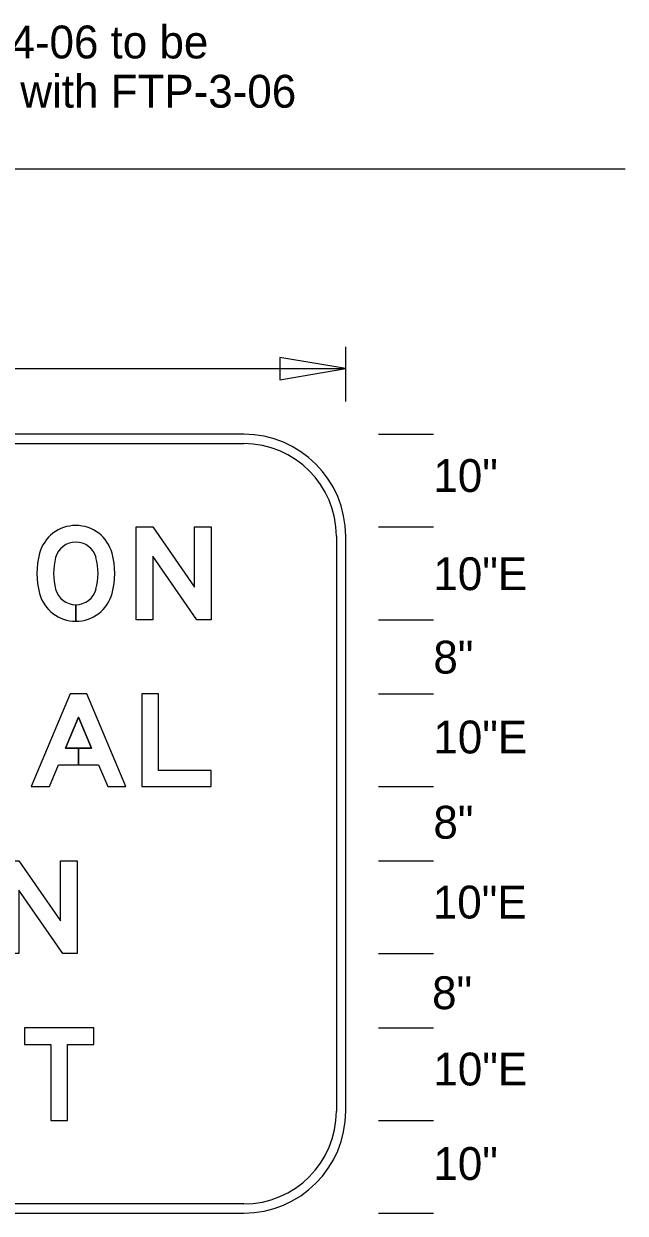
# Model space of a CAD drawing. Extents: x 0 to 770, y 0 to 495.
# Drawn here: x 705.9 to 770, y 218.8 to 345.5 of the extents above; entities that cross this region are included whole.
import ezdxf

# ---------------------------------------------------------------- set-up
doc = ezdxf.new("R2010")
doc.units = 0
for name, color, linetype in [('Dimension', 7, 'Continuous'), ('GSBWFill', 7, 'Continuous'), ('GSColorFill', 7, 'Continuous'), ('GSDims', 7, 'Continuous'), ('GSOutline', 7, 'Continuous'), ('SheetLines_dp', 7, 'Continuous'), ('TextStructures', 7, 'Continuous')]:
    doc.layers.add(name, color=color, linetype=linetype)

msp = doc.modelspace()

# ---------------------------------------------------------------- linework, layer by layer
at = {"layer": 'Dimension'}
msp.add_lwpolyline([(740.23, 308.76), (733.22, 309.95), (733.22, 307.57)], close=True, dxfattribs=at)
at = {"layer": 'GSBWFill'}
for p, q in [((729.36, 301.76), (608.82, 301.76)), ((729.36, 301.76), (608.82, 301.76)), ((608.82, 300.77), (729.36, 300.77)), ((739.25, 290.89), (739.25, 229.63)), ((740.23, 229.63), (740.23, 290.89)), ((740.23, 229.63), (740.23, 290.89)), ((711.48, 281.82), (711.48, 283.6)), ((711.48, 283.6), (711.48, 281.82)), ((729.36, 219.75), (608.83, 219.75)), ((608.82, 218.76), (729.36, 218.76)), ((608.83, 218.76), (729.36, 218.76))]:
    msp.add_line(p, q, dxfattribs=at)
for points in [[(725.91, 291.88), (725.91, 281.99), (724.37, 281.99), (719.68, 288.76), (719.68, 281.99), (717.9, 281.99), (717.9, 291.88), (719.69, 291.88), (724.13, 285.47), (724.13, 291.88)], [(713.16, 268.31), (711.78, 268.31), (711.78, 266.53), (713.91, 266.53), (714.89, 264.21), (716.82, 264.21), (712.67, 274.09), (710.89, 274.09), (706.74, 264.21), (708.67, 264.21), (709.64, 266.53), (711.78, 266.53), (711.78, 268.31), (710.39, 268.31), (711.78, 271.61)], [(725.91, 264.21), (725.91, 265.94), (720.27, 265.94), (720.27, 274.09), (718.5, 274.09), (718.5, 264.21)], [(711.63, 256.3), (711.63, 246.42), (710.1, 246.42), (705.4, 253.19), (705.4, 246.42), (703.62, 246.42), (703.62, 256.3), (705.41, 256.3), (709.85, 249.9), (709.85, 256.3)], [(706, 236.74), (708.81, 236.74), (708.81, 228.64), (710.59, 228.64), (710.59, 236.74), (713.41, 236.74), (713.41, 238.52), (706, 238.52)]]:
    msp.add_lwpolyline(points, close=True, dxfattribs=at)
for centre, radius, start, end in [((729.36, 290.89), 10.87, 0, 90), ((729.36, 290.89), 10.87, 0, 90), ((729.36, 290.89), 9.88, 0, 90), ((729.36, 229.63), 10.87, 270, 0), ((729.36, 229.63), 9.88, 270, 0), ((729.36, 229.63), 10.87, 270, 0)]:
    msp.add_arc(centre, radius, start, end, dxfattribs=at)
for centre, major_axis, start_param, end_param in [((711.48, 288.04), (0, 4), 4.973521, 7.592849), ((711.48, 288.04), (0, 2.23), 4.973521, 7.592849), ((715.63, 286.93), (0, 8.3), 1.309664, 1.831929), ((707.33, 286.93), (0, 8.3), 4.451257, 4.973521), ((715.63, 286.93), (0, 6.52), 1.309664, 1.831929), ((707.33, 286.93), (0, 6.52), 4.451257, 4.973521), ((711.48, 285.83), (0, 2.23), 1.831929, 3.141593), ((711.48, 285.83), (0, 2.23), 3.141815, 4.451257), ((711.48, 285.83), (0, 4), 1.831929, 3.141593), ((711.48, 285.83), (0, 4), 3.141716, 4.451257)]:
    msp.add_ellipse(centre, major_axis=major_axis, ratio=0.999994, start_param=start_param, end_param=end_param, dxfattribs=at)
at = {"layer": 'GSColorFill'}
for p, q in [((711.48, 281.82), (711.48, 283.6)), ((711.48, 283.6), (711.48, 281.82))]:
    msp.add_line(p, q, dxfattribs=at)
for points in [[(725.91, 291.88), (725.91, 281.99), (724.37, 281.99), (719.68, 288.76), (719.68, 281.99), (717.9, 281.99), (717.9, 291.88), (719.69, 291.88), (724.13, 285.47), (724.13, 291.88)], [(713.16, 268.31), (711.78, 268.31), (711.78, 266.53), (713.91, 266.53), (714.89, 264.21), (716.82, 264.21), (712.67, 274.09), (710.89, 274.09), (706.74, 264.21), (708.67, 264.21), (709.64, 266.53), (711.78, 266.53), (711.78, 268.31), (710.39, 268.31), (711.78, 271.61)], [(725.91, 264.21), (725.91, 265.94), (720.27, 265.94), (720.27, 274.09), (718.5, 274.09), (718.5, 264.21)], [(711.63, 256.3), (711.63, 246.42), (710.1, 246.42), (705.4, 253.19), (705.4, 246.42), (703.62, 246.42), (703.62, 256.3), (705.41, 256.3), (709.85, 249.9), (709.85, 256.3)], [(706, 236.74), (708.81, 236.74), (708.81, 228.64), (710.59, 228.64), (710.59, 236.74), (713.41, 236.74), (713.41, 238.52), (706, 238.52)]]:
    msp.add_lwpolyline(points, close=True, dxfattribs=at)
for centre, major_axis, start_param, end_param in [((711.48, 288.04), (0, 4), 4.973521, 7.592849), ((711.48, 288.04), (0, 2.23), 4.973521, 7.592849), ((715.63, 286.93), (0, 8.3), 1.309664, 1.831929), ((707.33, 286.93), (0, 8.3), 4.451257, 4.973521), ((715.63, 286.93), (0, 6.52), 1.309664, 1.831929), ((707.33, 286.93), (0, 6.52), 4.451257, 4.973521), ((711.48, 285.83), (0, 2.23), 1.831929, 3.141593), ((711.48, 285.83), (0, 2.23), 3.141815, 4.451257), ((711.48, 285.83), (0, 4), 1.831929, 3.141593), ((711.48, 285.83), (0, 4), 3.141716, 4.451257)]:
    msp.add_ellipse(centre, major_axis=major_axis, ratio=0.999994, start_param=start_param, end_param=end_param, dxfattribs=at)
at = {"layer": 'GSDims'}
for p, q in [((740.23, 305.26), (740.23, 311.09)), ((597.95, 308.76), (740.23, 308.76)), ((743.73, 301.76), (749.57, 301.76)), ((743.73, 291.88), (749.57, 291.88)), ((743.73, 291.88), (749.57, 291.88)), ((743.73, 281.99), (749.57, 281.99)), ((743.73, 281.99), (749.57, 281.99)), ((743.73, 274.09), (749.57, 274.09)), ((743.73, 274.09), (749.57, 274.09)), ((743.73, 264.21), (749.57, 264.21)), ((743.73, 264.21), (749.57, 264.21)), ((743.73, 256.3), (749.57, 256.3)), ((743.73, 256.3), (749.57, 256.3)), ((743.73, 246.42), (749.57, 246.42)), ((743.73, 246.42), (749.57, 246.42)), ((743.73, 238.52), (749.57, 238.52)), ((743.73, 238.52), (749.57, 238.52)), ((743.73, 228.64), (749.57, 228.64)), ((743.73, 228.64), (749.57, 228.64)), ((743.73, 218.76), (749.57, 218.76))]:
    msp.add_line(p, q, dxfattribs=at)
at = {"layer": 'GSOutline'}
for points in [[(725.91, 291.88), (725.91, 281.99), (724.37, 281.99), (719.68, 288.76), (719.68, 281.99), (717.9, 281.99), (717.9, 291.88), (719.69, 291.88), (724.13, 285.47), (724.13, 291.88)], [(709.64, 266.53), (713.91, 266.53), (714.89, 264.21), (716.82, 264.21), (712.67, 274.09), (710.89, 274.09), (706.74, 264.21), (708.67, 264.21)], [(725.91, 264.21), (725.91, 265.94), (720.27, 265.94), (720.27, 274.09), (718.5, 274.09), (718.5, 264.21)], [(713.16, 268.31), (711.78, 271.61), (710.39, 268.31)], [(711.63, 256.3), (711.63, 246.42), (710.1, 246.42), (705.4, 253.19), (705.4, 246.42), (703.62, 246.42), (703.62, 256.3), (705.41, 256.3), (709.85, 249.9), (709.85, 256.3)], [(706, 236.74), (708.81, 236.74), (708.81, 228.64), (710.59, 228.64), (710.59, 236.74), (713.41, 236.74), (713.41, 238.52), (706, 238.52)]]:
    msp.add_lwpolyline(points, close=True, dxfattribs=at)
for centre, major_axis, start_param, end_param in [((711.48, 288.04), (0, 4), 4.973521, 7.592849), ((711.48, 288.04), (0, 2.23), 4.973521, 7.592849), ((715.63, 286.93), (0, 8.3), 1.309664, 1.831929), ((707.33, 286.93), (0, 8.3), 4.451257, 4.973521), ((715.63, 286.93), (0, 6.52), 1.309664, 1.831929), ((707.33, 286.93), (0, 6.52), 4.451257, 4.973521), ((711.48, 285.83), (0, 2.23), 1.831929, 4.451257), ((711.48, 285.83), (0, 4), 1.831929, 4.451257)]:
    msp.add_ellipse(centre, major_axis=major_axis, ratio=0.999994, start_param=start_param, end_param=end_param, dxfattribs=at)
at = {"layer": 'SheetLines_dp'}
msp.add_line((770, 330), (0, 330), dxfattribs=at)

# ---------------------------------------------------------------- texts
at = {"layer": 'TextStructures'}
for s, p in [('FTP-4-06 to be ', (694.12, 341.81)), ('used with FTP-3-06', (694.12, 336.56)), ('10"', (749.57, 295.61)), ('10"E', (749.57, 285.15)), ('8"', (749.57, 276.26)), ('10"E', (749.57, 267.75)), ('8"', (749.57, 258.67)), ('10"E', (749.51, 250.16)), ('8"', (749.43, 240.5)), ('10"E', (749.57, 232.37)), ('10"', (749.57, 222.3))]:
    msp.add_text(s, height=3.5, dxfattribs=at).set_placement(p)

doc.saveas('drawing.dxf')
